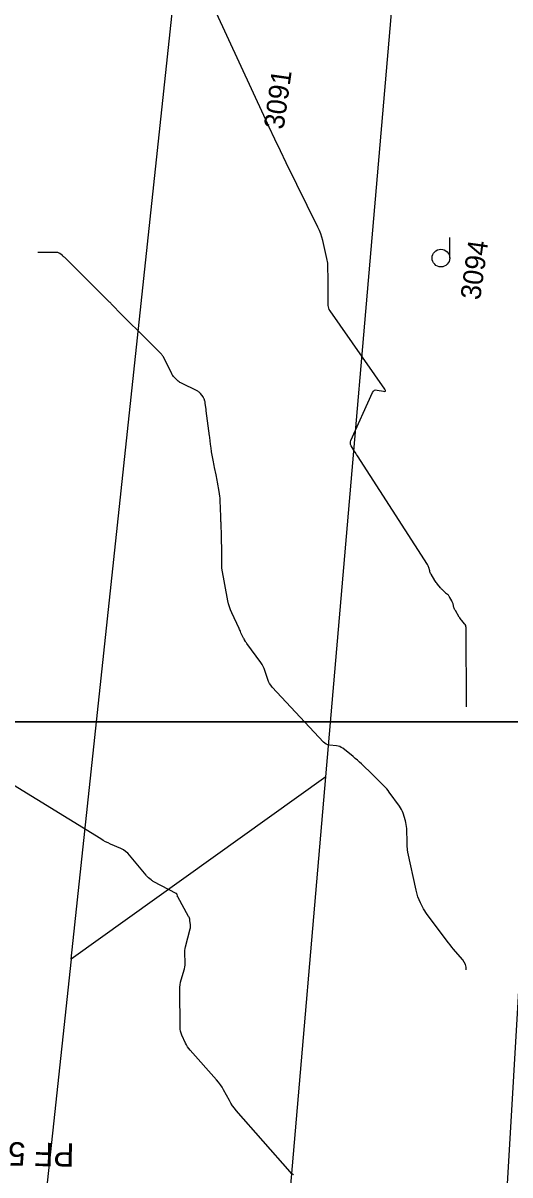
# Model space of a CAD drawing. Extents: x -534410 to -534262, y -1190162 to -1189584.
# Drawn here: x -534315.26 to -534294.49, y -1190023.79 to -1189974.68 of the extents above; entities that cross this region are included whole.
import ezdxf

# ---------------------------------------------------------------- set-up
doc = ezdxf.new("R2010")
doc.units = 0
for name, color, linetype in [('30', 7, 'Continuous'), ('31', 7, 'Continuous'), ('_N_text', 7, 'Continuous'), ('_rámeček', 7, 'Continuous'), ('Hranice parcel', 7, 'Continuous'), ('Parcelní čísla', 7, 'Continuous'), ('Značky kultur', 7, 'Continuous')]:
    doc.layers.add(name, color=color, linetype=linetype)

msp = doc.modelspace()

# ---------------------------------------------------------------- linework, layer by layer
at = {"layer": '30'}
msp.add_lwpolyline([(-534296.355, -1190015.043), (-534296.365, -1190014.928), (-534296.394, -1190014.819), (-534296.442, -1190014.717), (-534296.51, -1190014.623), (-534296.82, -1190014.259), (-534296.897, -1190014.167), (-534296.973, -1190014.075), (-534297.047, -1190013.981), (-534297.119, -1190013.886), (-534298.025, -1190012.678), (-534298.184, -1190012.441), (-534298.315, -1190012.191), (-534298.418, -1190011.929), (-534298.494, -1190011.654), (-534298.849, -1190010.027), (-534298.856, -1190009.995), (-534298.861, -1190009.964), (-534298.864, -1190009.933), (-534298.867, -1190009.901), (-534298.874, -1190009.774), (-534298.876, -1190009.742), (-534298.877, -1190009.71), (-534298.879, -1190009.678), (-534298.88, -1190009.646), (-534298.898, -1190009.012), (-534298.904, -1190008.929), (-534298.915, -1190008.846), (-534298.931, -1190008.765), (-534298.954, -1190008.685), (-534299.054, -1190008.365), (-534299.082, -1190008.287), (-534299.116, -1190008.211), (-534299.156, -1190008.139), (-534299.203, -1190008.07), (-534299.642, -1190007.466), (-534299.694, -1190007.398), (-534299.748, -1190007.332), (-534299.805, -1190007.268), (-534299.864, -1190007.207), (-534300.106, -1190006.965), (-534300.166, -1190006.905), (-534300.227, -1190006.845), (-534300.288, -1190006.785), (-534300.349, -1190006.726), (-534300.827, -1190006.265), (-534300.914, -1190006.183), (-534301.002, -1190006.104), (-534301.092, -1190006.027), (-534301.185, -1190005.951), (-534301.626, -1190005.6), (-534301.686, -1190005.558), (-534301.751, -1190005.525), (-534301.82, -1190005.503), (-534301.893, -1190005.49), (-534302.192, -1190005.458), (-534302.264, -1190005.445), (-534302.329, -1190005.419), (-534302.39, -1190005.382), (-534302.444, -1190005.333), (-534304.637, -1190002.987), (-534304.699, -1190002.913), (-534304.751, -1190002.834), (-534304.794, -1190002.749), (-534304.827, -1190002.659), (-534304.942, -1190002.287), (-534304.975, -1190002.196), (-534305.014, -1190002.109), (-534305.061, -1190002.025), (-534305.115, -1190001.945), (-534305.717, -1190001.125), (-534305.73, -1190001.107), (-534305.742, -1190001.088), (-534305.755, -1190001.07), (-534305.766, -1190001.051), (-534305.813, -1190000.975), (-534305.824, -1190000.956), (-534305.835, -1190000.937), (-534305.845, -1190000.917), (-534305.855, -1190000.897), (-534305.965, -1190000.67), (-534305.986, -1190000.625), (-534306.007, -1190000.58), (-534306.028, -1190000.535), (-534306.049, -1190000.49), (-534306.358, -1189999.828), (-534306.413, -1189999.701), (-534306.459, -1189999.571), (-534306.496, -1189999.439), (-534306.526, -1189999.305), (-534306.784, -1189997.912), (-534306.786, -1189997.901), (-534306.787, -1189997.889), (-534306.788, -1189997.878), (-534306.788, -1189997.867), (-534306.788, -1189997.076), (-534306.788, -1189996.96), (-534306.79, -1189996.845), (-534306.792, -1189996.729), (-534306.796, -1189996.613), (-534306.817, -1189995.96), (-534306.818, -1189995.94), (-534306.819, -1189995.92), (-534306.82, -1189995.9), (-534306.821, -1189995.879), (-534306.827, -1189995.799), (-534306.828, -1189995.778), (-534306.829, -1189995.758), (-534306.83, -1189995.738), (-534306.831, -1189995.718), (-534306.855, -1189995.035), (-534306.86, -1189994.94), (-534306.868, -1189994.845), (-534306.879, -1189994.75), (-534306.894, -1189994.656), (-534306.963, -1189994.249), (-534306.977, -1189994.17), (-534306.991, -1189994.091), (-534307.007, -1189994.013), (-534307.023, -1189993.934), (-534307.09, -1189993.619), (-534307.106, -1189993.542), (-534307.122, -1189993.464), (-534307.137, -1189993.387), (-534307.151, -1189993.31), (-534307.216, -1189992.956), (-534307.225, -1189992.9), (-534307.234, -1189992.844), (-534307.243, -1189992.788), (-534307.25, -1189992.732), (-534307.278, -1189992.506), (-534307.285, -1189992.45), (-534307.292, -1189992.393), (-534307.299, -1189992.337), (-534307.306, -1189992.28), (-534307.447, -1189991.203), (-534307.451, -1189991.167), (-534307.456, -1189991.131), (-534307.461, -1189991.096), (-534307.465, -1189991.06), (-534307.486, -1189990.894), (-534307.489, -1189990.869), (-534307.494, -1189990.845), (-534307.5, -1189990.821), (-534307.507, -1189990.797), (-534307.538, -1189990.703), (-534307.547, -1189990.679), (-534307.558, -1189990.657), (-534307.57, -1189990.636), (-534307.584, -1189990.616), (-534307.696, -1189990.471), (-534307.721, -1189990.442), (-534307.749, -1189990.417), (-534307.779, -1189990.394), (-534307.812, -1189990.375), (-534308.529, -1189990.017), (-534308.569, -1189989.995), (-534308.607, -1189989.97), (-534308.644, -1189989.941), (-534308.677, -1189989.91), (-534308.809, -1189989.779), (-534308.84, -1189989.745), (-534308.868, -1189989.709), (-534308.894, -1189989.671), (-534308.916, -1189989.63), (-534309.274, -1189988.913), (-534309.293, -1189988.88), (-534309.313, -1189988.848), (-534309.337, -1189988.818), (-534309.362, -1189988.789), (-534309.469, -1189988.679), (-534309.496, -1189988.652), (-534309.523, -1189988.624), (-534309.55, -1189988.597), (-534309.578, -1189988.571), (-534309.688, -1189988.463), (-534309.715, -1189988.437), (-534309.743, -1189988.41), (-534309.77, -1189988.383), (-534309.797, -1189988.356), (-534311.254, -1189986.899), (-534311.281, -1189986.872), (-534311.308, -1189986.844), (-534311.335, -1189986.817), (-534311.362, -1189986.789), (-534311.469, -1189986.679), (-534311.496, -1189986.652), (-534311.523, -1189986.624), (-534311.55, -1189986.597), (-534311.578, -1189986.571), (-534311.688, -1189986.463), (-534311.716, -1189986.437), (-534311.743, -1189986.41), (-534311.77, -1189986.383), (-534311.797, -1189986.356), (-534313.254, -1189984.899), (-534313.281, -1189984.872), (-534313.309, -1189984.845), (-534313.336, -1189984.818), (-534313.364, -1189984.791), (-534313.481, -1189984.679), (-534313.505, -1189984.655), (-534313.531, -1189984.632), (-534313.557, -1189984.61), (-534313.583, -1189984.589), (-534313.69, -1189984.503), (-534313.717, -1189984.485), (-534313.747, -1189984.471), (-534313.778, -1189984.463), (-534313.811, -1189984.461), (-534314.628, -1189984.461)], dxfattribs=at)
at = {"layer": '31'}
for points in [[(-534296.349, -1190003.825), (-534296.366, -1190000.45), (-534296.37, -1190000.406), (-534296.381, -1190000.364), (-534296.4, -1190000.325), (-534296.427, -1190000.289), (-534296.547, -1190000.151), (-534296.577, -1190000.116), (-534296.605, -1190000.079), (-534296.631, -1190000.042), (-534296.656, -1190000.003), (-534296.823, -1189999.727), (-534296.841, -1189999.695), (-534296.857, -1189999.661), (-534296.87, -1189999.627), (-534296.881, -1189999.591), (-534296.921, -1189999.44), (-534296.931, -1189999.408), (-534296.943, -1189999.377), (-534296.957, -1189999.347), (-534296.973, -1189999.318), (-534297.063, -1189999.168), (-534297.07, -1189999.157), (-534297.077, -1189999.145), (-534297.084, -1189999.133), (-534297.091, -1189999.121), (-534297.117, -1189999.073), (-534297.125, -1189999.062), (-534297.133, -1189999.052), (-534297.143, -1189999.043), (-534297.155, -1189999.036), (-534297.203, -1189999.009), (-534297.214, -1189999.002), (-534297.225, -1189998.994), (-534297.236, -1189998.985), (-534297.246, -1189998.976), (-534297.363, -1189998.855), (-534297.385, -1189998.831), (-534297.407, -1189998.807), (-534297.429, -1189998.783), (-534297.45, -1189998.758), (-534297.586, -1189998.597), (-534297.614, -1189998.561), (-534297.642, -1189998.524), (-534297.668, -1189998.486), (-534297.692, -1189998.448), (-534297.86, -1189998.172), (-534297.878, -1189998.139), (-534297.894, -1189998.106), (-534297.907, -1189998.072), (-534297.918, -1189998.036), (-534297.956, -1189997.892), (-534297.967, -1189997.857), (-534297.981, -1189997.822), (-534297.997, -1189997.789), (-534298.016, -1189997.757), (-534301, -1189993.126), (-534301.034, -1189993.073), (-534301.068, -1189993.02), (-534301.101, -1189992.967), (-534301.133, -1189992.913), (-534301.263, -1189992.698), (-534301.288, -1189992.643), (-534301.298, -1189992.588), (-534301.294, -1189992.532), (-534301.276, -1189992.475), (-534300.352, -1189990.422), (-534300.318, -1189990.367), (-534300.274, -1189990.333), (-534300.22, -1189990.317), (-534300.156, -1189990.322), (-534299.881, -1189990.378), (-534299.826, -1189990.383), (-534299.798, -1189990.37), (-534299.797, -1189990.339), (-534299.824, -1189990.291), (-534302.166, -1189986.949), (-534302.198, -1189986.895), (-534302.222, -1189986.839), (-534302.236, -1189986.779), (-534302.243, -1189986.717), (-534302.25, -1189986.462), (-534302.251, -1189986.398), (-534302.253, -1189986.334), (-534302.253, -1189986.27), (-534302.253, -1189986.207), (-534302.253, -1189985.482), (-534302.254, -1189985.419), (-534302.254, -1189985.355), (-534302.256, -1189985.291), (-534302.257, -1189985.227), (-534302.265, -1189984.972), (-534302.268, -1189984.908), (-534302.275, -1189984.845), (-534302.285, -1189984.783), (-534302.298, -1189984.72), (-534302.479, -1189983.949), (-534302.518, -1189983.801), (-534302.566, -1189983.657), (-534302.621, -1189983.515), (-534302.685, -1189983.376), (-534304.033, -1189980.634), (-534304.278, -1189980.13), (-534304.521, -1189979.625), (-534304.76, -1189979.119), (-534304.997, -1189978.611), (-534309.554, -1189968.746)], [(-534303.73, -1190023.791), (-534303.805, -1190023.73), (-534303.872, -1190023.66), (-534306.164, -1190021.04), (-534306.246, -1190020.94), (-534306.323, -1190020.836), (-534306.394, -1190020.728), (-534306.459, -1190020.617), (-534306.707, -1190020.161), (-534306.772, -1190020.049), (-534306.843, -1190019.941), (-534306.92, -1190019.838), (-534307.004, -1190019.739), (-534308.134, -1190018.469), (-534308.192, -1190018.398), (-534308.245, -1190018.324), (-534308.291, -1190018.246), (-534308.332, -1190018.164), (-534308.485, -1190017.83), (-534308.519, -1190017.746), (-534308.543, -1190017.659), (-534308.558, -1190017.57), (-534308.563, -1190017.479), (-534308.574, -1190015.894), (-534308.571, -1190015.786), (-534308.56, -1190015.679), (-534308.542, -1190015.574), (-534308.515, -1190015.469), (-534308.377, -1190014.995), (-534308.358, -1190014.92), (-534308.346, -1190014.843), (-534308.341, -1190014.766), (-534308.342, -1190014.688), (-534308.361, -1190014.374), (-534308.363, -1190014.295), (-534308.359, -1190014.218), (-534308.348, -1190014.141), (-534308.331, -1190014.064), (-534308.133, -1190013.301), (-534308.124, -1190013.256), (-534308.119, -1190013.211), (-534308.118, -1190013.165), (-534308.121, -1190013.12), (-534308.144, -1190012.936), (-534308.152, -1190012.891), (-534308.164, -1190012.847), (-534308.18, -1190012.805), (-534308.201, -1190012.764), (-534308.661, -1190011.938), (-534308.667, -1190011.925), (-534308.673, -1190011.912), (-534308.677, -1190011.899), (-534308.68, -1190011.885), (-534308.692, -1190011.828), (-534308.696, -1190011.814), (-534308.703, -1190011.803), (-534308.712, -1190011.794), (-534308.724, -1190011.786), (-534309.678, -1190011.291), (-534309.71, -1190011.273), (-534309.741, -1190011.254), (-534309.771, -1190011.233), (-534309.799, -1190011.21), (-534309.912, -1190011.116), (-534309.939, -1190011.092), (-534309.966, -1190011.067), (-534309.991, -1190011.04), (-534310.014, -1190011.013), (-534310.717, -1190010.154), (-534310.797, -1190010.067), (-534310.885, -1190009.992), (-534310.982, -1190009.927), (-534311.087, -1190009.874), (-534311.524, -1190009.685), (-534311.633, -1190009.635), (-534311.739, -1190009.582), (-534311.844, -1190009.526), (-534311.946, -1190009.465), (-534317.42, -1190006.098)]]:
    msp.add_lwpolyline(points, dxfattribs=at)
at = {"layer": '_rámeček'}
for points in [[(-534410.126, -1189899.47), (-534261.626, -1189899.47), (-534261.626, -1190004.47), (-534410.126, -1190004.47)], [(-534410.126, -1190004.47), (-534261.626, -1190004.47), (-534261.626, -1190109.47), (-534410.126, -1190109.47)]]:
    msp.add_lwpolyline(points, close=True, dxfattribs=at)
at = {"layer": 'Hranice parcel'}
for p, q in [((-534313.21, -1190014.59), (-534305.87, -1189945.8)), ((-534302.34, -1190006.82), (-534297.16, -1189946.38)), ((-534290.08, -1189946.94), (-534297.41, -1190071.61)), ((-534302.34, -1190006.82), (-534313.21, -1190014.59)), ((-534307.49, -1190066.49), (-534302.34, -1190006.82))]:
    msp.add_line(p, q, dxfattribs=at)
msp.add_lwpolyline([(-534313.21, -1190014.59), (-534315.24, -1190033.54), (-534318.8, -1190033.53)], dxfattribs=at)
at = {"layer": 'Značky kultur'}
msp.add_line((-534297.064, -1189984.696), (-534297.064, -1189983.821), dxfattribs=at)
msp.add_circle((-534297.439, -1189984.696), 0.375, dxfattribs=at)

# ---------------------------------------------------------------- texts
at = {"layer": '_N_text'}
msp.add_text('PF 5', height=1, rotation=178.8836, dxfattribs=at).set_placement((-534313.063, -1190022.442))
at = {"layer": 'Parcelní čísla'}
for s, p in [('3091', (-534304.152, -1189979.242)), ('3094', (-534295.77, -1189986.511))]:
    msp.add_text(s, height=0.85, rotation=82, dxfattribs=at).set_placement(p)

doc.saveas('drawing.dxf')
